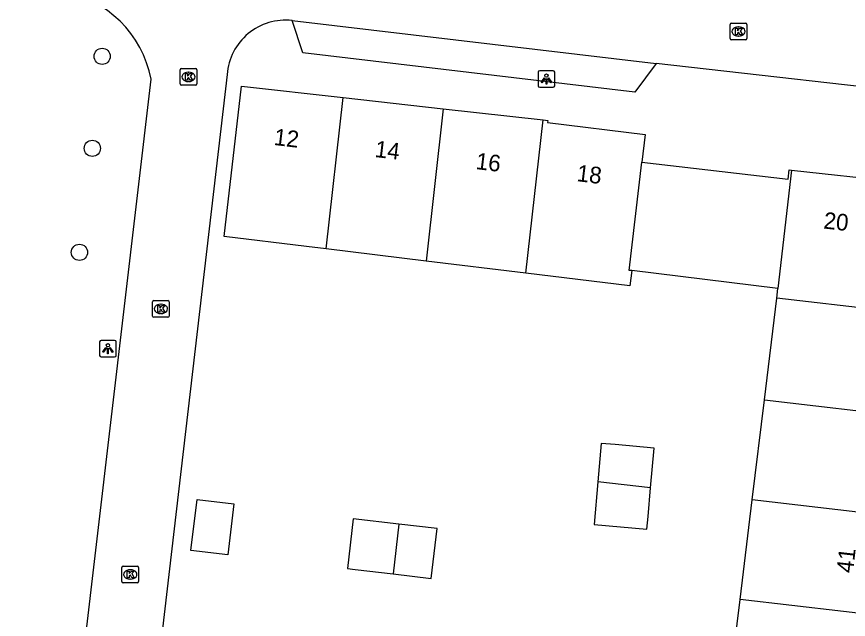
# Model space of a CAD drawing. Extents: x 161243 to 161752, y 384138 to 384885.
# Drawn here: x 161329.4 to 161379.5, y 384394.5 to 384430.7 of the extents above; entities that cross this region are included whole.
import ezdxf

# ---------------------------------------------------------------- set-up
doc = ezdxf.new("R2010")
doc.units = 0
for name, color, linetype in [('IMGEO_Boom', 7, 'Continuous'), ('IMGEO_Kolk', 7, 'Continuous'), ('IMGEO_Lichtpunt', 7, 'Continuous'), ('IMGEO_Pand', 7, 'Continuous'), ('IMGEO_Pand_nummerreeks', 7, 'Continuous'), ('IMGEO_Parkeervlak_open', 7, 'Continuous'), ('IMGEO_Rijbaan_lokaal_open', 7, 'Continuous')]:
    doc.layers.add(name, color=color, linetype=linetype)

msp = doc.modelspace()

# ---------------------------------------------------------------- linework, layer by layer
at = {"layer": 'IMGEO_Boom'}
for centre in [(161334.587, 384428.343), (161333.994, 384422.809), (161333.221, 384416.553)]:
    msp.add_circle(centre, 0.489, dxfattribs=at)
at = {"layer": 'IMGEO_Kolk'}
for p, q in [((161372.364, 384429.412), (161372.364, 384430.264)), ((161372.439, 384430.338), (161373.291, 384430.338)), ((161372.852, 384430.118), (161372.877, 384430.118)), ((161373.365, 384430.264), (161373.365, 384429.412)), ((161372.875, 384429.558), (161372.85, 384429.558)), ((161373.291, 384429.338), (161372.439, 384429.338)), ((161339.28, 384426.68), (161339.28, 384427.532)), ((161339.355, 384427.606), (161340.207, 384427.606)), ((161340.281, 384427.532), (161340.281, 384426.68)), ((161339.768, 384427.386), (161339.793, 384427.386)), ((161340.207, 384426.606), (161339.355, 384426.606)), ((161339.791, 384426.826), (161339.766, 384426.826)), ((161337.618, 384412.721), (161337.618, 384413.573)), ((161337.693, 384413.647), (161338.545, 384413.647)), ((161338.106, 384413.427), (161338.131, 384413.427)), ((161338.619, 384413.573), (161338.619, 384412.721)), ((161338.545, 384412.647), (161337.693, 384412.647)), ((161338.129, 384412.867), (161338.104, 384412.867)), ((161335.775, 384396.75), (161335.775, 384397.602)), ((161335.85, 384397.676), (161336.702, 384397.676)), ((161336.263, 384397.456), (161336.288, 384397.456)), ((161336.776, 384397.602), (161336.776, 384396.75)), ((161336.286, 384396.896), (161336.261, 384396.896)), ((161336.702, 384396.676), (161335.85, 384396.676))]:
    msp.add_line(p, q, dxfattribs=at)
for points in [[(161372.364, 384429.412), (161372.364, 384430.264)], [(161372.439, 384430.338), (161373.291, 384430.338)], [(161372.685, 384430.038), (161372.808, 384430.038), (161372.808, 384429.887), (161372.938, 384430.038), (161373.102, 384430.038), (161372.956, 384429.887), (161373.109, 384429.638), (161372.957, 384429.638), (161372.872, 384429.802), (161372.808, 384429.735), (161372.808, 384429.638), (161372.685, 384429.638), (161372.685, 384430.038)], [(161373.365, 384430.264), (161373.365, 384429.412)], [(161373.291, 384429.338), (161372.439, 384429.338)], [(161339.28, 384426.68), (161339.28, 384427.532)], [(161339.355, 384427.606), (161340.207, 384427.606)], [(161340.281, 384427.532), (161340.281, 384426.68)], [(161339.601, 384427.306), (161339.724, 384427.306), (161339.724, 384427.155), (161339.854, 384427.306), (161340.018, 384427.306), (161339.872, 384427.155), (161340.025, 384426.906), (161339.873, 384426.906), (161339.788, 384427.07), (161339.724, 384427.003), (161339.724, 384426.906), (161339.601, 384426.906), (161339.601, 384427.306)], [(161340.207, 384426.606), (161339.355, 384426.606)], [(161337.618, 384412.721), (161337.618, 384413.573)], [(161337.693, 384413.647), (161338.545, 384413.647)], [(161338.619, 384413.573), (161338.619, 384412.721)], [(161337.939, 384413.347), (161338.062, 384413.347), (161338.062, 384413.196), (161338.192, 384413.347), (161338.356, 384413.347), (161338.21, 384413.196), (161338.363, 384412.947), (161338.211, 384412.947), (161338.126, 384413.111), (161338.062, 384413.044), (161338.062, 384412.947), (161337.939, 384412.947), (161337.939, 384413.347)], [(161338.545, 384412.647), (161337.693, 384412.647)], [(161335.775, 384396.75), (161335.775, 384397.602)], [(161335.85, 384397.676), (161336.702, 384397.676)], [(161336.096, 384397.376), (161336.219, 384397.376), (161336.219, 384397.225), (161336.349, 384397.376), (161336.513, 384397.376), (161336.367, 384397.225), (161336.52, 384396.976), (161336.368, 384396.976), (161336.283, 384397.14), (161336.219, 384397.073), (161336.219, 384396.976), (161336.096, 384396.976), (161336.096, 384397.376)], [(161336.776, 384397.602), (161336.776, 384396.75)], [(161336.702, 384396.676), (161335.85, 384396.676)]]:
    msp.add_lwpolyline(points, dxfattribs=at)
for centre, start, end in [((161372.441, 384430.262), 91.552, 178.448), ((161372.441, 384430.262), 91.552, 178.448), ((161373.289, 384430.262), 1.552, 88.448), ((161373.289, 384430.262), 1.552, 88.448), ((161372.441, 384429.414), 181.552, 268.448), ((161372.441, 384429.414), 181.552, 268.448), ((161373.289, 384429.414), 271.552, 358.448), ((161373.289, 384429.414), 271.552, 358.448), ((161339.357, 384427.53), 91.552, 178.448), ((161339.357, 384427.53), 91.552, 178.448), ((161340.205, 384427.53), 1.552, 88.448), ((161340.205, 384427.53), 1.552, 88.448), ((161339.357, 384426.682), 181.552, 268.448), ((161339.357, 384426.682), 181.552, 268.448), ((161340.205, 384426.682), 271.552, 358.448), ((161340.205, 384426.682), 271.552, 358.448), ((161337.695, 384413.571), 91.552, 178.448), ((161337.695, 384413.571), 91.552, 178.448), ((161338.543, 384413.571), 1.552, 88.448), ((161338.543, 384413.571), 1.552, 88.448), ((161337.695, 384412.723), 181.552, 268.448), ((161337.695, 384412.723), 181.552, 268.448), ((161338.543, 384412.723), 271.552, 358.448), ((161338.543, 384412.723), 271.552, 358.448), ((161335.852, 384397.6), 91.552, 178.448), ((161335.852, 384397.6), 91.552, 178.448), ((161336.7, 384397.6), 1.552, 88.448), ((161336.7, 384397.6), 1.552, 88.448), ((161335.852, 384396.752), 181.552, 268.448), ((161335.852, 384396.752), 181.552, 268.448), ((161336.7, 384396.752), 271.552, 358.448), ((161336.7, 384396.752), 271.552, 358.448)]:
    msp.add_arc(centre, 0.0765, start, end, dxfattribs=at)
for centre, major_axis, ratio, start_param, end_param in [((161372.851, 384429.838), (-0.387, 0.002), 0.722429, 4.712389, 7.853982), ((161372.876, 384429.838), (-0.39, 0.002), 0.717154, 1.570796, 4.712389), ((161339.767, 384427.106), (-0.387, 0.002), 0.722429, 4.712389, 7.853982), ((161339.792, 384427.106), (-0.39, 0.002), 0.717154, 1.570796, 4.712389), ((161338.105, 384413.147), (-0.387, 0.002), 0.722429, 4.712389, 7.853982), ((161338.13, 384413.147), (-0.39, 0.002), 0.717154, 1.570796, 4.712389), ((161336.262, 384397.176), (-0.387, 0.002), 0.722429, 4.712389, 7.853982), ((161336.287, 384397.176), (-0.39, 0.002), 0.717154, 1.570796, 4.712389)]:
    msp.add_ellipse(centre, major_axis=major_axis, ratio=ratio, start_param=start_param, end_param=end_param, dxfattribs=at)
at = {"layer": 'IMGEO_Lichtpunt'}
for p, q in [((161361.715, 384427.479), (161360.907, 384427.479)), ((161361.715, 384427.479), (161360.907, 384427.479)), ((161360.813, 384427.384), (161360.813, 384426.577)), ((161360.813, 384427.384), (161360.813, 384426.577)), ((161361.809, 384426.577), (161361.809, 384427.384)), ((161361.809, 384426.577), (161361.809, 384427.384)), ((161360.907, 384426.483), (161361.715, 384426.483)), ((161360.907, 384426.483), (161361.715, 384426.483)), ((161334.432, 384411.162), (161334.432, 384410.355)), ((161334.432, 384411.162), (161334.432, 384410.355)), ((161335.334, 384411.257), (161334.526, 384411.257)), ((161335.334, 384411.257), (161334.526, 384411.257)), ((161335.428, 384410.355), (161335.428, 384411.162)), ((161335.428, 384410.355), (161335.428, 384411.162)), ((161334.526, 384410.261), (161335.334, 384410.261)), ((161334.526, 384410.261), (161335.334, 384410.261))]:
    msp.add_line(p, q, dxfattribs=at)
for points in [[(161361.187, 384427.048), (161361.226, 384427.02), (161361.038, 384426.758), (161361, 384426.785), (161361.187, 384427.048)], [(161361.289, 384427), (161361.336, 384427), (161361.336, 384426.678), (161361.289, 384426.678), (161361.289, 384427)], [(161361.399, 384427.02), (161361.437, 384427.047), (161361.624, 384426.785), (161361.585, 384426.757), (161361.399, 384427.02)], [(161334.806, 384410.826), (161334.845, 384410.798), (161334.657, 384410.536), (161334.619, 384410.563), (161334.806, 384410.826)], [(161334.908, 384410.778), (161334.955, 384410.778), (161334.955, 384410.456), (161334.908, 384410.456), (161334.908, 384410.778)], [(161335.018, 384410.798), (161335.056, 384410.825), (161335.243, 384410.563), (161335.204, 384410.535), (161335.018, 384410.798)]]:
    msp.add_lwpolyline(points, dxfattribs=at)
for centre in [(161361.312, 384427.182), (161334.931, 384410.96)]:
    msp.add_circle(centre, 0.0994, dxfattribs=at)
for centre, start, end in [((161360.907, 384427.384), 90, 180), ((161360.907, 384427.384), 90, 180), ((161361.715, 384427.384), 0, 90), ((161361.715, 384427.384), 0, 90), ((161360.907, 384426.577), 180, 270), ((161360.907, 384426.577), 180, 270), ((161361.715, 384426.577), 270, 0), ((161361.715, 384426.577), 270, 360), ((161334.526, 384411.162), 90, 180), ((161334.526, 384411.162), 90, 180), ((161335.334, 384411.162), 0, 90), ((161335.334, 384411.162), 0, 90), ((161334.526, 384410.355), 180, 270), ((161334.526, 384410.355), 180, 270), ((161335.334, 384410.355), 270, 0), ((161335.334, 384410.355), 270, 360)]:
    msp.add_arc(centre, 0.0946, start, end, dxfattribs=at)
at = {"layer": 'IMGEO_Pand'}
for points in [[(161348.06, 384416.76), (161346.882, 384416.903), (161341.924, 384417.506), (161342.972, 384426.55), (161349.081, 384425.866)], [(161348.06, 384416.76), (161349.081, 384425.866)], [(161349.081, 384425.866), (161355.094, 384425.192)], [(161355.094, 384425.192), (161354.067, 384416.029)], [(161355.094, 384425.192), (161361.107, 384424.518)], [(161360.073, 384415.299), (161361.107, 384424.518)], [(161361.107, 384424.518), (161361.387, 384424.487), (161361.374, 384424.373), (161367.249, 384423.645), (161367.047, 384421.971)], [(161366.442, 384415.451), (161366.294, 384415.469), (161367.047, 384421.971)], [(161367.047, 384421.971), (161375.849, 384420.952), (161375.912, 384421.508), (161376.061, 384421.492)], [(161376.061, 384421.492), (161375.237, 384414.381)], [(161376.061, 384421.492), (161382.318, 384420.819), (161381.408, 384413.065)], [(161354.067, 384416.029), (161348.06, 384416.76)], [(161360.073, 384415.299), (161354.067, 384416.029)], [(161366.442, 384415.451), (161366.331, 384414.538), (161360.073, 384415.299)], [(161375.237, 384414.381), (161366.442, 384415.451)], [(161375.166, 384413.798), (161375.237, 384414.381)], [(161374.421, 384407.672), (161375.166, 384413.798)], [(161381.408, 384413.065), (161375.166, 384413.798)], [(161373.691, 384401.666), (161374.421, 384407.672)], [(161374.421, 384407.672), (161383.357, 384406.631)], [(161367.576, 384402.378), (161367.785, 384404.779), (161365.449, 384404.983), (161364.609, 384405.056), (161364.407, 384402.747)], [(161364.407, 384402.747), (161364.181, 384400.173), (161367.359, 384399.895), (161367.426, 384400.665), (161367.576, 384402.378)], [(161367.576, 384402.378), (161364.407, 384402.747)], [(161342.142, 384398.35), (161339.927, 384398.607), (161340.293, 384401.675), (161342.498, 384401.419), (161342.142, 384398.35)], [(161372.96, 384395.661), (161373.691, 384401.666)], [(161382.786, 384400.607), (161373.691, 384401.666)], [(161352.441, 384400.203), (161349.691, 384400.523), (161349.343, 384397.529), (161349.797, 384397.476), (161352.092, 384397.209)], [(161352.441, 384400.203), (161352.092, 384397.209)], [(161352.092, 384397.209), (161354.386, 384396.941), (161354.736, 384399.936), (161352.441, 384400.203)], [(161372.23, 384389.655), (161372.96, 384395.661)], [(161382.283, 384394.576), (161372.96, 384395.661)]]:
    msp.add_lwpolyline(points, dxfattribs=at)
at = {"layer": 'IMGEO_Parkeervlak_open'}
msp.add_lwpolyline([(161367.914, 384427.91), (161366.618, 384426.186), (161346.658, 384428.547), (161346.013, 384430.497)], dxfattribs=at)
at = {"layer": 'IMGEO_Rijbaan_lokaal_open'}
for points in [[(161346.013, 384430.497), (161367.914, 384427.91)], [(161385.608, 384425.915), (161367.914, 384427.91)], [(161329.442, 384358.011), (161337.531, 384426.972)], [(161342.1, 384427.256), (161334.846, 384365.031)]]:
    msp.add_lwpolyline(points, dxfattribs=at)
for centre, radius, start, end in [((161331.055, 384425.741), 6.592, 10.7616, 80.6019), ((161345.619, 384426.99), 3.529, 83.5883, 175.6792)]:
    msp.add_arc(centre, radius, start, end, dxfattribs=at)

# ---------------------------------------------------------------- texts
at = {"layer": 'IMGEO_Pand_nummerreeks'}
for s, rotation, p in [('12', 353.1764, (161344.883, 384423.017)), ('14', 353.1764, (161350.955, 384422.291)), ('16', 353.1764, (161357.025, 384421.565)), ('18', 353.1764, (161363.097, 384420.839)), ('20', 353.8611, (161377.946, 384417.99)), ('41', 83.3755, (161379.744, 384397.228))]:
    msp.add_text(s, height=1, rotation=rotation, dxfattribs=at).set_placement(p)

doc.saveas('drawing.dxf')
